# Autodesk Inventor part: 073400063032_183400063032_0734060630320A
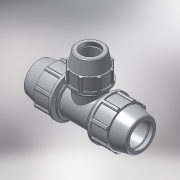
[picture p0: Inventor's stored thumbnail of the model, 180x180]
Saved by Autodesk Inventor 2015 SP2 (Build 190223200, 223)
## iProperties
Created: 2017-02
Part Number: 073400063032_183400063032_0734060630320A
Material: PVC-Piping
Description: PLASSON REDUCING TEE 63-32-63
Document SubType Name: Modeling
Designer: KIM
Mass: 92.6774 g
Surface Area: 199.44 cm^2
Volume: 66.1981 cm^3
Density: 1.4 g/cm^3
Appearance: Smooth - White
Author: Кирилл
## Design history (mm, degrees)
derived "07340.ipt"
feature "Solid1::07340.ipt"
feature "Solid2::07340.ipt"
tag "TaggingFeature1"
body "Solid1"
other parameters: "d2" = 63, "d4" = 11.16667, "d5" = 37.52, "d7" = 113, "d11" = 4.46667, "d13" = 120 deg, "d14" = 88.2, "d15" = 12 deg, "d16" = 98.31, "d18" = 3.15, "d19" = 35 deg, "d20" = 17.5 deg, "d21" = 105.09, "d23" = 0, "d25" = 360 deg, "d27" = 2.26, "d33" = 1.26, "d42" = 48.24, "d43" = 3.39, "d46" = 1.89, "d67" = 84.75, "d76" = 32, "d77" = 64, "d78" = 12 deg, "d79" = 118, "d80" = 120 deg, "d81" = 44.8, "d82" = 9.83333, "d87" = 3.93333, "d89" = 29.5, "d90" = 35.4, "d96" = 22.33333, "d98" = 59.52, "d99" = 35 deg, "d100" = 17.5 deg, "d102" = 0, "d103" = 1.28, "d107" = 360 deg, "d109" = 0.96, "d112" = 1.6, "d113" = 4.26667, "d114" = 0, "d117" = 268, "d118" = 55.68, "d126" = 56.7, "d127" = 113, "d131" = 4.72, "d132" = 28.8, "d133" = 62, "d135" = 0, "d138" = 5.36, "d143" = 0, "d148" = 48, "d168" = 56.7, "d170" = 0, "d171" = 32, "d173" = 0, "d175" = 0, "d176" = 4.26667, "d177" = 0, "d_" = 63, "E_" = 113, "A_" = 118, "l_" = 113, "E_1" = 64, "l_1" = 62, "d_1" = 32, "H_" = 268
